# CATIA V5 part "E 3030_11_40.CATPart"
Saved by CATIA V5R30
Part number: Operka
Definition: E 3030_11_40
Nomenclature: E 3030_11_40
Source: Unknown
Description: PART--DESC
Bounding box of the stored display mesh (mm): x -4.004 to 4.257, y -11 to 0, z -20 to 20
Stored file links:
  E:\Bakalarka\Model\Forma_v7\E 3030_11_40.CATPart
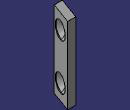
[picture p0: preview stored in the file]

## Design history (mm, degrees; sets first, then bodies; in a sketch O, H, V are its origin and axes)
Body1 "MANIFOLD_SOLID_BREP #221" (main body)
  Solid1: solid without history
